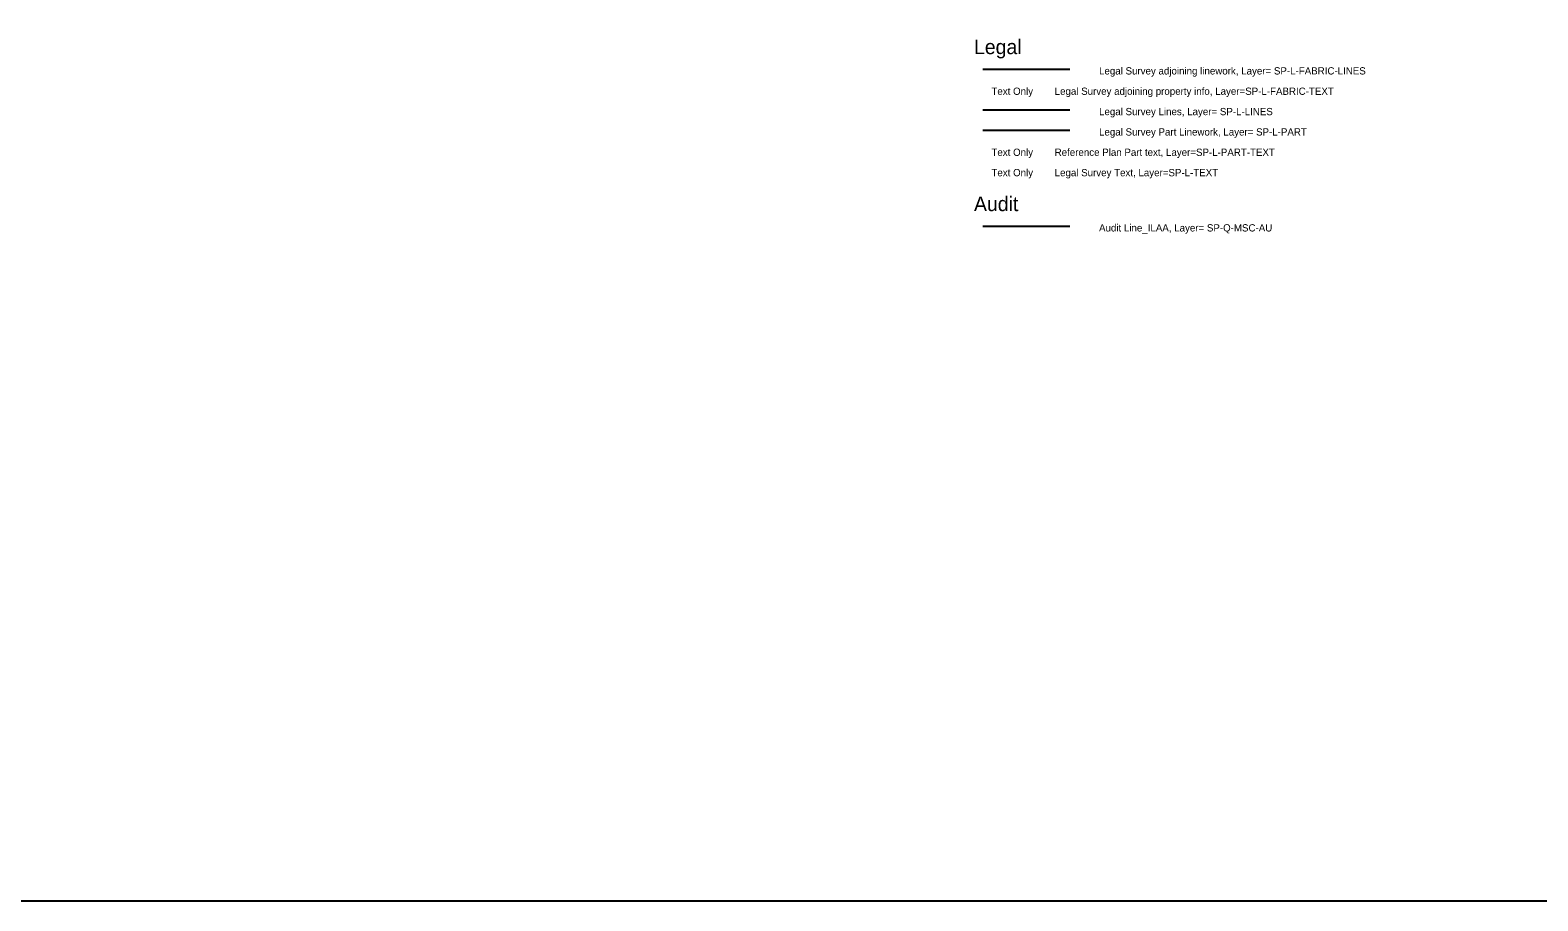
# Model space of a CAD drawing. Extents: x 500528 to 502626, y 4210261 to 4212624.
# Drawn here: x 501059 to 501577, y 4210261 to 4210560 of the extents above; entities that cross this region are included whole.
import ezdxf

# ---------------------------------------------------------------- set-up
doc = ezdxf.new("R2010")
doc.units = 0
for name, color, linetype in [('Default', 7, 'Continuous'), ('SP-L-FABRIC-LINES', 7, 'Continuous'), ('SP-L-FABRIC-TEXT', 7, 'Continuous'), ('SP-L-LINES', 7, 'Continuous'), ('SP-L-PART', 7, 'Continuous'), ('SP-L-PART-TEXT', 7, 'Continuous'), ('SP-L-TEXT', 7, 'Continuous'), ('SP-Q-MSC-AU', 7, 'Continuous')]:
    doc.layers.add(name, color=color, linetype=linetype)

msp = doc.modelspace()

# ---------------------------------------------------------------- linework, layer by layer
at = {"layer": 'Default'}
msp.add_lwpolyline([(500528.35, 4212623.85), (500528.35, 4210260.5), (502626.48, 4210260.5), (502626.48, 4212623.85), (500528.35, 4212623.85)], dxfattribs=at)
msp.add_lwpolyline([(500528.35, 4210260.5), (502626.48, 4210260.5), (502626.48, 4212623.85), (500528.35, 4212623.85)], close=True, dxfattribs=at)
at = {"layer": 'SP-L-FABRIC-LINES'}
msp.add_line((501386.55, 4210546.59), (501416.55, 4210546.59), dxfattribs=at)
at = {"layer": 'SP-L-LINES'}
msp.add_line((501386.55, 4210532.59), (501416.55, 4210532.59), dxfattribs=at)
at = {"layer": 'SP-L-PART'}
msp.add_line((501386.55, 4210525.59), (501416.55, 4210525.59), dxfattribs=at)
at = {"layer": 'SP-Q-MSC-AU'}
msp.add_line((501386.55, 4210492.59), (501416.55, 4210492.59), dxfattribs=at)

# ---------------------------------------------------------------- texts
at = {"layer": 'Default'}
for s, p in [('Legal  ', (501383.55, 4210551.74)), ('Audit ', (501383.55, 4210497.74))]:
    msp.add_text(s, height=5, dxfattribs=at).set_placement(p)
at = {"layer": 'SP-L-FABRIC-LINES'}
msp.add_text('Legal Survey adjoining linework, Layer= SP-L-FABRIC-LINES ', height=2.5, dxfattribs=at).set_placement((501426.55, 4210544.74))
at = {"layer": 'SP-L-FABRIC-TEXT'}
msp.add_text('Text Only        Legal Survey adjoining property info, Layer=SP-L-FABRIC-TEXT', height=2.5, dxfattribs=at).set_placement((501389.55, 4210537.74))
at = {"layer": 'SP-L-LINES'}
msp.add_text('Legal Survey Lines, Layer= SP-L-LINES ', height=2.5, dxfattribs=at).set_placement((501426.55, 4210530.74))
at = {"layer": 'SP-L-PART'}
msp.add_text('Legal Survey Part Linework, Layer= SP-L-PART ', height=2.5, dxfattribs=at).set_placement((501426.55, 4210523.74))
at = {"layer": 'SP-L-PART-TEXT'}
msp.add_text('Text Only        Reference Plan Part text, Layer=SP-L-PART-TEXT', height=2.5, dxfattribs=at).set_placement((501389.55, 4210516.74))
at = {"layer": 'SP-L-TEXT'}
msp.add_text('Text Only        Legal Survey Text, Layer=SP-L-TEXT', height=2.5, dxfattribs=at).set_placement((501389.55, 4210509.74))
at = {"layer": 'SP-Q-MSC-AU'}
msp.add_text('Audit Line_ILAA, Layer= SP-Q-MSC-AU ', height=2.5, dxfattribs=at).set_placement((501426.55, 4210490.74))

doc.saveas('drawing.dxf')
